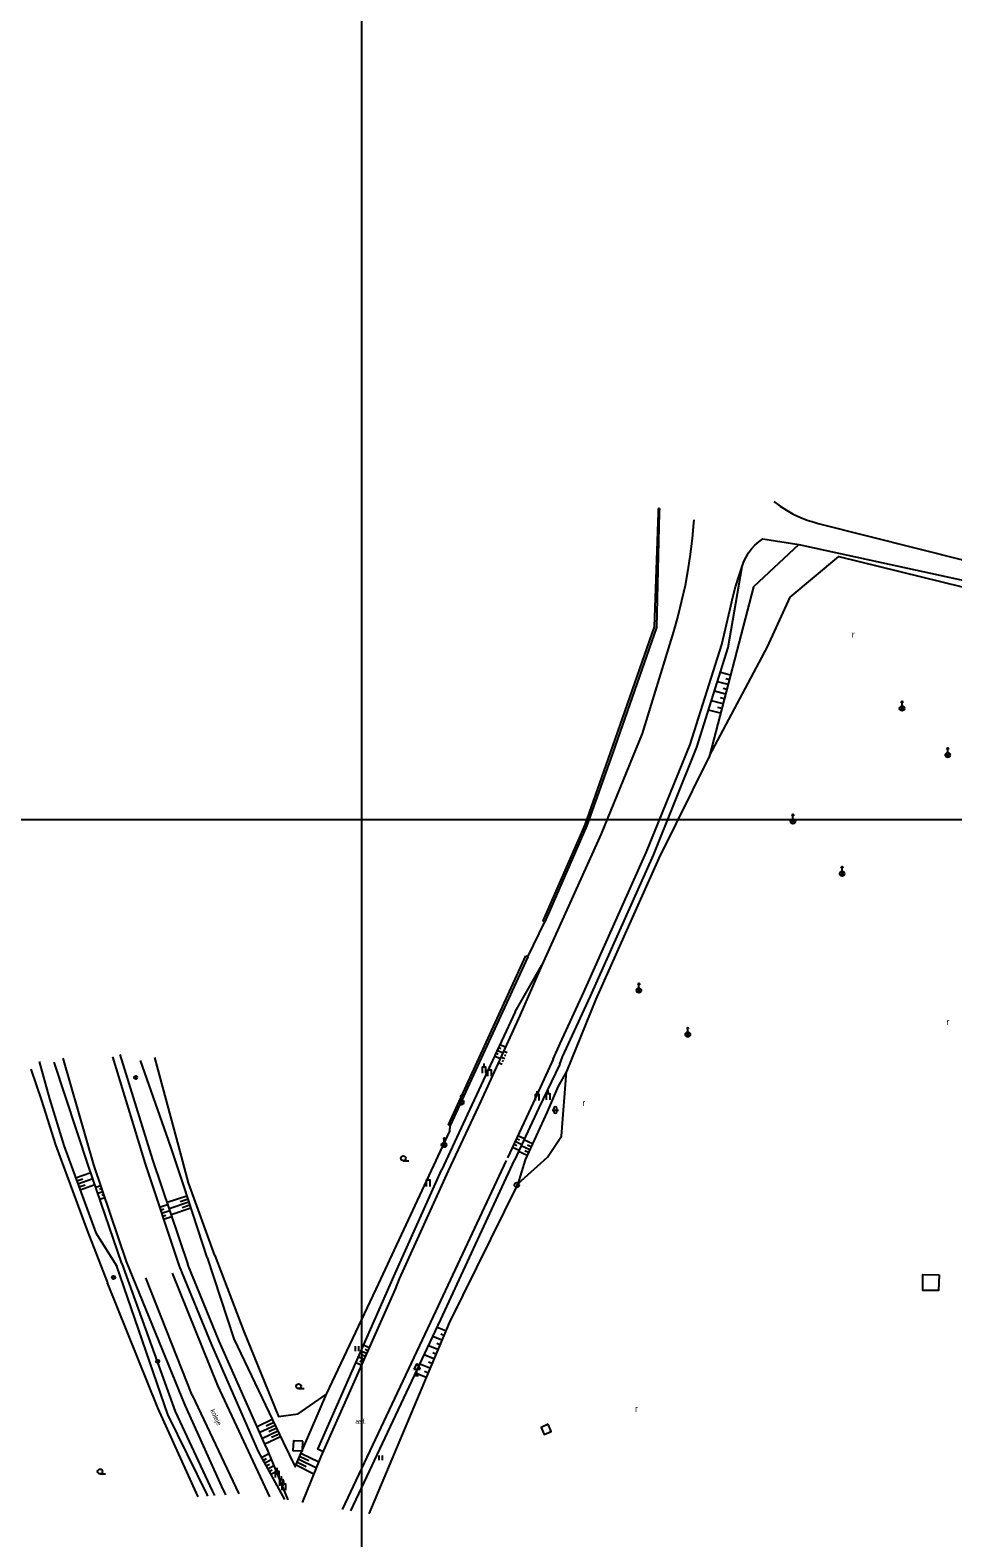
# Model space of a CAD drawing. Extents: x -582188 to -561562, y -1187250 to -1183500.
# Drawn here: x -562864.4 to -562719.9, y -1186612.4 to -1186376.4 of the extents above; entities that cross this region are included whole.
import ezdxf

# ---------------------------------------------------------------- set-up
doc = ezdxf.new("R2010")
doc.units = 0
for name, color, linetype in [('MAP_ZN_BP', 7, 'Continuous'), ('POMOC_POPIS', 7, 'Continuous'), ('ROZHRANÍ_PLOCH', 7, 'Continuous'), ('RÁMY_ML', 7, 'Continuous'), ('VÝŠKOPIS', 7, 'Continuous'), ('ZELEŇ', 7, 'Continuous'), ('ZN_BP', 7, 'Continuous'), ('ZN_DOPLŇKOVÉ', 7, 'Continuous'), ('ZN_KULTUR', 7, 'Continuous')]:
    doc.layers.add(name, color=color, linetype=linetype)

msp = doc.modelspace()

# ---------------------------------------------------------------- linework, layer by layer
at = {"layer": 'MAP_ZN_BP'}
for radius in [0.375, 0.0005]:
    msp.add_circle((-562788.18, -1186557.181), radius, dxfattribs=at)
at = {"layer": 'ROZHRANÍ_PLOCH'}
for points in [[(-562747.89, -1186450.19), (-562746.94, -1186450.9), (-562745.94, -1186451.55), (-562744.9, -1186452.13), (-562743.82, -1186452.64), (-562742.71, -1186453.07), (-562741.58, -1186453.43), (-562740.98, -1186453.59), (-562717.94, -1186459.43)], [(-562760.46, -1186453.05), (-562760.49, -1186453.49), (-562760.7, -1186455.96), (-562761, -1186458.42), (-562761.37, -1186460.87), (-562761.82, -1186463.31), (-562762.35, -1186465.73), (-562762.96, -1186468.14), (-562763.65, -1186470.52), (-562768.52, -1186486.48), (-562774.96, -1186502.19), (-562784.26, -1186522.79)], [(-562777.7, -1186527.02), (-562767.84, -1186505), (-562761.01, -1186488.24), (-562756.06, -1186472.58), (-562754.57, -1186466.31), (-562754.33, -1186465.17), (-562753.91, -1186463.54), (-562753.42, -1186461.93), (-562752.85, -1186460.35), (-562752.59, -1186459.59), (-562752.26, -1186458.88), (-562751.86, -1186458.2), (-562751.4, -1186457.58), (-562750.87, -1186457), (-562750.28, -1186456.48), (-562749.65, -1186456.02), (-562744.02, -1186456.89), (-562718.1, -1186462.54)], [(-562784.26, -1186522.79), (-562787.65, -1186530.57)], [(-562782.46, -1186537.51), (-562781.36, -1186535.04), (-562777.7, -1186527.02)], [(-562787.65, -1186530.57), (-562793.86, -1186544.16), (-562798.93, -1186554.97)], [(-562850.37, -1186536.76), (-562845.22, -1186553.23), (-562839.7, -1186569.64)], [(-562782.46, -1186537.51), (-562785.62, -1186544.35), (-562789.63, -1186552.96)], [(-562850.04, -1186569.49), (-562855.26, -1186554.23), (-562860.63, -1186537.98)], [(-562815.47, -1186607.99), (-562801.25, -1186577.77), (-562789.8, -1186553.36)], [(-562798.93, -1186554.97), (-562806.59, -1186571.88), (-562807.25, -1186573.49), (-562818.85, -1186599.69), (-562821.78, -1186606.9)], [(-562722.03, -1186571.26), (-562722.14, -1186573.69), (-562724.58, -1186573.69), (-562724.58, -1186571.18), (-562722.03, -1186571.26)]]:
    msp.add_lwpolyline(points, dxfattribs=at)
at = {"layer": 'RÁMY_ML'}
msp.add_line((-562812.5, -1186250), (-562812.5, -1186750), dxfattribs=at)
msp.add_lwpolyline([(-562187.5, -1186500), (-563750, -1186500), (-564062.5, -1186500), (-564375, -1186500), (-564687.5, -1186500), (-565000, -1186500)], dxfattribs=at)
at = {"layer": 'VÝŠKOPIS'}
for p, q in [((-562788.44, -1186530.08), (-562784.26, -1186522.79)), ((-562790.81, -1186535.18), (-562789.94, -1186535.58)), ((-562791.65, -1186536.99), (-562790.77, -1186537.4)), ((-562791.44, -1186536.54), (-562791.09, -1186536.7)), ((-562791.23, -1186536.09), (-562790.36, -1186536.49)), ((-562791.02, -1186535.63), (-562790.67, -1186535.8)), ((-562790.07, -1186537.41), (-562790.66, -1186537.15)), ((-562789.67, -1186536.5), (-562790.24, -1186536.24)), ((-562789.87, -1186536.95), (-562790.09, -1186536.86)), ((-562790.47, -1186538.33), (-562791.07, -1186538.06)), ((-562790.27, -1186537.87), (-562790.49, -1186537.77)), ((-562780.37, -1186539.4), (-562781.71, -1186541.7)), ((-562787.99, -1186549.45), (-562786.95, -1186549.93)), ((-562788.84, -1186551.26), (-562787.8, -1186551.74)), ((-562788.63, -1186550.81), (-562788.17, -1186551.02)), ((-562788.42, -1186550.35), (-562787.37, -1186550.84)), ((-562788.2, -1186549.9), (-562787.75, -1186550.11)), ((-562786.14, -1186551.66), (-562787.47, -1186551.04)), ((-562785.72, -1186550.75), (-562787.05, -1186550.14)), ((-562785.93, -1186551.21), (-562786.48, -1186550.95)), ((-562786.56, -1186552.57), (-562787.89, -1186551.95)), ((-562786.35, -1186552.11), (-562786.9, -1186551.86)), ((-562857.28, -1186556.09), (-562854.92, -1186555.23)), ((-562857.1, -1186556.56), (-562856.16, -1186556.21)), ((-562856.93, -1186557.03), (-562854.6, -1186556.17)), ((-562856.76, -1186557.5), (-562855.81, -1186557.15)), ((-562856.59, -1186557.97), (-562854.27, -1186557.12)), ((-562853.34, -1186557.3), (-562854.12, -1186557.57)), ((-562853.02, -1186558.25), (-562853.79, -1186558.52)), ((-562853.18, -1186557.78), (-562853.52, -1186557.89)), ((-562852.86, -1186558.72), (-562853.19, -1186558.84)), ((-562839.84, -1186558.92), (-562842.96, -1186559.95)), ((-562852.69, -1186559.2), (-562853.47, -1186559.46)), ((-562844.13, -1186560.64), (-562842.87, -1186560.22)), ((-562843.98, -1186561.11), (-562843.46, -1186560.94)), ((-562843.82, -1186561.59), (-562842.55, -1186561.17)), ((-562839.53, -1186559.87), (-562842.64, -1186560.9)), ((-562839.22, -1186560.82), (-562842.32, -1186561.84)), ((-562839.68, -1186559.4), (-562840.9, -1186559.8)), ((-562839.37, -1186560.35), (-562840.59, -1186560.75)), ((-562843.66, -1186562.06), (-562843.14, -1186561.89)), ((-562843.5, -1186562.53), (-562842.23, -1186562.11)), ((-562811.32, -1186582.67), (-562812.19, -1186582.29)), ((-562799.94, -1186581.49), (-562801.32, -1186580.92)), ((-562811.52, -1186583.13), (-562811.95, -1186582.94)), ((-562802.09, -1186586.61), (-562802.62, -1186586.39)), ((-562801.47, -1186585.15), (-562801.99, -1186584.94)), ((-562826.26, -1186594.37), (-562827.45, -1186594.94)), ((-562827.42, -1186598.22), (-562824.06, -1186606.51)), ((-562827.44, -1186601.17), (-562826.94, -1186600.9)), ((-562822.75, -1186601.03), (-562819.95, -1186602.4)), ((-562822.31, -1186600.14), (-562819.57, -1186601.47)), ((-562826.95, -1186602.05), (-562826.51, -1186601.81))]:
    msp.add_line(p, q, dxfattribs=at)
for points in [[(-562744.02, -1186456.89), (-562751.11, -1186463.52), (-562757.97, -1186490)], [(-562776.61, -1186527.61), (-562766.77, -1186505.52), (-562759.98, -1186488.66), (-562755.05, -1186473.04), (-562752.85, -1186460.35)], [(-562755.08, -1186478.84), (-562756.74, -1186478.41)], [(-562754.69, -1186477.34), (-562756.28, -1186476.93)], [(-562754.88, -1186478.09), (-562755.43, -1186477.95)], [(-562755.47, -1186480.33), (-562757.21, -1186479.88)], [(-562755.66, -1186481.08), (-562756.25, -1186480.93)], [(-562755.27, -1186479.59), (-562755.84, -1186479.44)], [(-562756.24, -1186483.33), (-562758.14, -1186482.83)], [(-562755.85, -1186481.83), (-562757.68, -1186481.36)], [(-562756.05, -1186482.58), (-562756.67, -1186482.42)], [(-562781.43, -1186538.28), (-562781.03, -1186537.11), (-562776.61, -1186527.61)], [(-562788.44, -1186530.08), (-562794.85, -1186543.87), (-562799.98, -1186554.85)], [(-562849.3, -1186569.19), (-562854.45, -1186554.03), (-562859.25, -1186537.34)], [(-562851.52, -1186537.12), (-562846.37, -1186553.88), (-562841.07, -1186569.89)], [(-562862.99, -1186537.84), (-562861.38, -1186543.7), (-562859.14, -1186551), (-562854.12, -1186564.7), (-562850.84, -1186569.89)], [(-562836.69, -1186568.53), (-562840.41, -1186557.18), (-562842.36, -1186551.21), (-562847.1, -1186537.7)], [(-562781.43, -1186538.28), (-562784.71, -1186545.13), (-562788.52, -1186553.29)], [(-562781.71, -1186541.7), (-562783.4, -1186545.75), (-562786.88, -1186553.26)], [(-562814.18, -1186608.21), (-562800.05, -1186578.23), (-562788.52, -1186553.29)], [(-562786.88, -1186553.26), (-562788.01, -1186556.99)], [(-562818.5, -1186598.98), (-562819.34, -1186598.57), (-562807.46, -1186571.51), (-562799.98, -1186554.85)], [(-562836.56, -1186605.91), (-562836.67, -1186605.67), (-562842.84, -1186593.12), (-562850.84, -1186569.89)], [(-562850.04, -1186569.49), (-562841.71, -1186592.67), (-562835.89, -1186605.05), (-562835.51, -1186605.83)], [(-562833.75, -1186605.7), (-562834.4, -1186604.39), (-562840.11, -1186591.64), (-562849.3, -1186569.19)], [(-562841.07, -1186569.89), (-562835.99, -1186582.21), (-562828.67, -1186598.93), (-562824.54, -1186606.43)], [(-562827.42, -1186598.22), (-562834.82, -1186581.62), (-562839.7, -1186569.64)], [(-562836.69, -1186568.53), (-562832.5, -1186581.25), (-562824.79, -1186597.47), (-562822.88, -1186601.3), (-562818.01, -1186589.94)], [(-562799.33, -1186580.03), (-562800.64, -1186579.48)], [(-562800.55, -1186582.96), (-562801.99, -1186582.35)], [(-562800.25, -1186582.23), (-562800.72, -1186582.03)], [(-562799.63, -1186580.76), (-562800.08, -1186580.57)], [(-562812.13, -1186584.5), (-562813, -1186584.12)], [(-562812.33, -1186584.96), (-562812.76, -1186584.77)], [(-562811.72, -1186583.59), (-562812.59, -1186583.2)], [(-562811.92, -1186584.05), (-562812.36, -1186583.85)], [(-562801.17, -1186584.42), (-562802.67, -1186583.79)], [(-562800.86, -1186583.69), (-562801.35, -1186583.48)], [(-562812.53, -1186585.42), (-562813.4, -1186585.03)], [(-562802.39, -1186587.34), (-562804.02, -1186586.66)], [(-562801.78, -1186585.88), (-562803.35, -1186585.22)], [(-562826.48, -1186593.92), (-562828.84, -1186595.04)], [(-562826.05, -1186594.82), (-562828.43, -1186595.96)], [(-562825.62, -1186595.73), (-562828.02, -1186596.87)], [(-562825.19, -1186596.63), (-562827.62, -1186597.78)], [(-562825.83, -1186595.27), (-562827.03, -1186595.84)], [(-562825.4, -1186596.18), (-562826.61, -1186596.75)], [(-562828.16, -1186599.86), (-562827.01, -1186599.23)], [(-562827.92, -1186600.3), (-562827.37, -1186600)], [(-562827.68, -1186600.74), (-562826.63, -1186600.16)], [(-562827.19, -1186601.61), (-562826.26, -1186601.09)], [(-562822.53, -1186600.59), (-562821.15, -1186601.26)], [(-562822.1, -1186599.69), (-562820.74, -1186600.35)], [(-562821.88, -1186599.24), (-562819.19, -1186600.54)], [(-562826.71, -1186602.49), (-562825.88, -1186602.03)]]:
    msp.add_lwpolyline(points, dxfattribs=at)
at = {"layer": 'ZELEŇ'}
msp.add_line((-562775.79, -1186528.07), (-562780.37, -1186539.4), dxfattribs=at)
for points in [[(-562757.97, -1186490), (-562748.88, -1186472.92), (-562745.36, -1186465.16), (-562737.74, -1186458.78), (-562718.42, -1186463.52)], [(-562757.97, -1186490), (-562765.95, -1186505.99), (-562775.79, -1186528.07)], [(-562788.01, -1186556.99), (-562783.36, -1186552.82), (-562781.18, -1186549.56), (-562780.37, -1186539.4)], [(-562788.01, -1186556.99), (-562798.79, -1186578.75), (-562811.35, -1186608.7)]]:
    msp.add_lwpolyline(points, dxfattribs=at)
at = {"layer": 'ZN_BP'}
for p, q in [((-562728.095, -1186482.834), (-562727.566, -1186482.306)), ((-562727.566, -1186482.838), (-562728.095, -1186482.306)), ((-562727.83, -1186482.195), (-562727.83, -1186481.445)), ((-562720.935, -1186490.134), (-562720.406, -1186489.606)), ((-562720.406, -1186490.138), (-562720.935, -1186489.606)), ((-562720.67, -1186489.495), (-562720.67, -1186488.745)), ((-562744.91, -1186499.865), (-562744.91, -1186499.115)), ((-562745.175, -1186500.504), (-562744.646, -1186499.976)), ((-562744.646, -1186500.508), (-562745.175, -1186499.976)), ((-562737.485, -1186508.704), (-562736.956, -1186508.176)), ((-562736.956, -1186508.708), (-562737.485, -1186508.176)), ((-562737.22, -1186508.065), (-562737.22, -1186507.315)), ((-562769.05, -1186526.345), (-562769.05, -1186525.595)), ((-562769.315, -1186526.984), (-562768.786, -1186526.456)), ((-562768.786, -1186526.988), (-562769.315, -1186526.456)), ((-562761.38, -1186533.255), (-562761.38, -1186532.505)), ((-562761.645, -1186533.894), (-562761.116, -1186533.366)), ((-562761.116, -1186533.898), (-562761.645, -1186533.366)), ((-562797.125, -1186544.504), (-562796.596, -1186543.976)), ((-562796.596, -1186544.508), (-562797.125, -1186543.976)), ((-562796.86, -1186543.865), (-562796.86, -1186543.115)), ((-562799.835, -1186551.174), (-562799.306, -1186550.646)), ((-562799.306, -1186551.178), (-562799.835, -1186550.646)), ((-562799.57, -1186550.535), (-562799.57, -1186549.785))]:
    msp.add_line(p, q, dxfattribs=at)
for points in [[(-562727.955, -1186481.695), (-562727.83, -1186481.445), (-562727.705, -1186481.695)], [(-562720.795, -1186488.995), (-562720.67, -1186488.745), (-562720.545, -1186488.995)], [(-562745.035, -1186499.365), (-562744.91, -1186499.115), (-562744.785, -1186499.365)], [(-562737.345, -1186507.565), (-562737.22, -1186507.315), (-562737.095, -1186507.565)], [(-562769.175, -1186525.845), (-562769.05, -1186525.595), (-562768.925, -1186525.845)], [(-562761.505, -1186532.755), (-562761.38, -1186532.505), (-562761.255, -1186532.755)], [(-562796.985, -1186543.365), (-562796.86, -1186543.115), (-562796.735, -1186543.365)], [(-562799.695, -1186550.035), (-562799.57, -1186549.785), (-562799.445, -1186550.035)]]:
    msp.add_lwpolyline(points, dxfattribs=at)
for centre in [(-562727.83, -1186482.57), (-562720.67, -1186489.87), (-562744.91, -1186500.24), (-562737.22, -1186508.44), (-562769.05, -1186526.72), (-562761.38, -1186533.63), (-562796.86, -1186544.24), (-562799.57, -1186550.91)]:
    msp.add_circle(centre, 0.375, dxfattribs=at)
at = {"layer": 'ZN_DOPLŇKOVÉ'}
for p, q in [((-562766, -1186451.89), (-562765.98, -1186451.29)), ((-562765.83, -1186451.29), (-562765.85, -1186451.89)), ((-562793.31, -1186538.69), (-562793.31, -1186538.19)), ((-562792.46, -1186539.14), (-562792.46, -1186538.64)), ((-562783.26, -1186542.86), (-562783.26, -1186542.36)), ((-562784.97, -1186542.98), (-562784.97, -1186542.48)), ((-562802.05, -1186556.4), (-562802.05, -1186555.9)), ((-562835.48, -1186568.21), (-562830.94, -1186580.14)), ((-562803.81, -1186585.154), (-562804.31, -1186586.02)), ((-562804.31, -1186586.02), (-562803.31, -1186586.02)), ((-562804.06, -1186587.02), (-562803.56, -1186587.02)), ((-562803.81, -1186585.154), (-562803.31, -1186586.02)), ((-562803.81, -1186587.02), (-562803.81, -1186586.02)), ((-562826.84, -1186606.03), (-562835, -1186588.57)), ((-562839.04, -1186590.09), (-562831.73, -1186605.55)), ((-562838.09, -1186606.03), (-562844.4, -1186592.1)), ((-562825.72, -1186602), (-562825.72, -1186601.5)), ((-562825.06, -1186603.29), (-562825.06, -1186602.79)), ((-562824.66, -1186603.97), (-562824.66, -1186603.47))]:
    msp.add_line(p, q, dxfattribs=at)
for points in [[(-562783.79, -1186515.96), (-562784.06, -1186515.84), (-562777.46, -1186500.79), (-562773.48, -1186489.51), (-562766.58, -1186469.78), (-562766, -1186451.89)], [(-562765.85, -1186451.89), (-562766.3, -1186469.88), (-562773.2, -1186489.61), (-562777.18, -1186500.9), (-562783.79, -1186515.96)], [(-562765.83, -1186451.29), (-562765.98, -1186451.29)], [(-562786.47, -1186521.45), (-562783.79, -1186515.96)], [(-562798.62, -1186547.87), (-562798.89, -1186547.75), (-562786.74, -1186521.33)], [(-562786.47, -1186521.45), (-562798.62, -1186547.87)], [(-562786.74, -1186521.33), (-562786.47, -1186521.45)], [(-562835.48, -1186568.21), (-562839.59, -1186556.87), (-562841.11, -1186551.14), (-562844.86, -1186537.25)], [(-562864.31, -1186539.03), (-562862.65, -1186543.98), (-562860.45, -1186550.9), (-562855.49, -1186564.31), (-562852.3, -1186572.52)], [(-562793.56, -1186539.69), (-562793.56, -1186538.69), (-562793.06, -1186538.69), (-562793.06, -1186539.69)], [(-562792.71, -1186540.14), (-562792.71, -1186539.14), (-562792.21, -1186539.14), (-562792.21, -1186540.14)], [(-562785.22, -1186543.98), (-562785.22, -1186542.98), (-562784.72, -1186542.98), (-562784.72, -1186543.98)], [(-562783.51, -1186543.86), (-562783.51, -1186542.86), (-562783.01, -1186542.86), (-562783.01, -1186543.86)], [(-562830.94, -1186580.14), (-562825.49, -1186593.44), (-562822.4, -1186593.04), (-562818.01, -1186589.94), (-562810.22, -1186573.48), (-562798.66, -1186548.77), (-562798.62, -1186547.87)], [(-562802.3, -1186557.4), (-562802.3, -1186556.4), (-562801.8, -1186556.4), (-562801.8, -1186557.4)], [(-562844.4, -1186592.1), (-562852.3, -1186572.52)], [(-562839.04, -1186590.09), (-562846.27, -1186571.73)], [(-562835, -1186588.57), (-562842.12, -1186571.01)], [(-562783.26, -1186594.63), (-562784.37, -1186595.14), (-562783.88, -1186596.25), (-562782.8, -1186595.81), (-562783.26, -1186594.63)], [(-562821.68, -1186597.28), (-562823.17, -1186597.26), (-562823.24, -1186598.76), (-562821.73, -1186598.82), (-562821.68, -1186597.28)], [(-562825.97, -1186603), (-562825.97, -1186602), (-562825.47, -1186602), (-562825.47, -1186603)], [(-562825.31, -1186604.29), (-562825.31, -1186603.29), (-562824.81, -1186603.29), (-562824.81, -1186604.29)], [(-562824.91, -1186604.97), (-562824.91, -1186603.97), (-562824.41, -1186603.97), (-562824.41, -1186604.97)]]:
    msp.add_lwpolyline(points, dxfattribs=at)
for centre, radius in [((-562847.87, -1186540.36), 0.25), ((-562847.87, -1186540.36), 0.0005), ((-562851.341, -1186571.66), 0.25), ((-562851.341, -1186571.66), 0.0005), ((-562844.421, -1186584.81), 0.25), ((-562844.421, -1186584.81), 0.0005)]:
    msp.add_circle(centre, radius, dxfattribs=at)
at = {"layer": 'ZN_KULTUR'}
for p, q in [((-562782.64, -1186545.45), (-562781.64, -1186545.45)), ((-562782.39, -1186545.7), (-562782.39, -1186545.2)), ((-562781.89, -1186545.7), (-562781.89, -1186545.2)), ((-562805.95, -1186553.395), (-562805.075, -1186553.395)), ((-562813.44, -1186583.185), (-562813.44, -1186582.435)), ((-562812.94, -1186583.185), (-562812.94, -1186582.435)), ((-562822.35, -1186589.075), (-562821.475, -1186589.075)), ((-562809.73, -1186600.285), (-562809.73, -1186599.535)), ((-562809.23, -1186600.285), (-562809.23, -1186599.535)), ((-562853.46, -1186602.425), (-562852.585, -1186602.425))]:
    msp.add_line(p, q, dxfattribs=at)
for centre in [(-562805.95, -1186553.02), (-562822.35, -1186588.7), (-562853.46, -1186602.05)]:
    msp.add_circle(centre, 0.375, dxfattribs=at)
for centre, start, end in [((-562782.14, -1186545.2), 0, 179.99999), ((-562782.14, -1186545.7), 179.99999, 359.99999)]:
    msp.add_arc(centre, 0.25, start, end, dxfattribs=at)

# ---------------------------------------------------------------- texts
at = {"layer": 'POMOC_POPIS'}
msp.add_text('koleje', height=0.75, rotation=295.325, dxfattribs=at).set_placement((-562836.21, -1186592.49))
msp.add_text('asf.', height=0.75, dxfattribs=at).set_placement((-562813.46, -1186594.56))
at = {"layer": 'ZN_KULTUR'}
for p in [(-562735.698, -1186471.482), (-562720.868, -1186532.122), (-562777.908, -1186544.842), (-562769.668, -1186592.712)]:
    msp.add_text('r', height=1, dxfattribs=at).set_placement(p)

doc.saveas('drawing.dxf')
